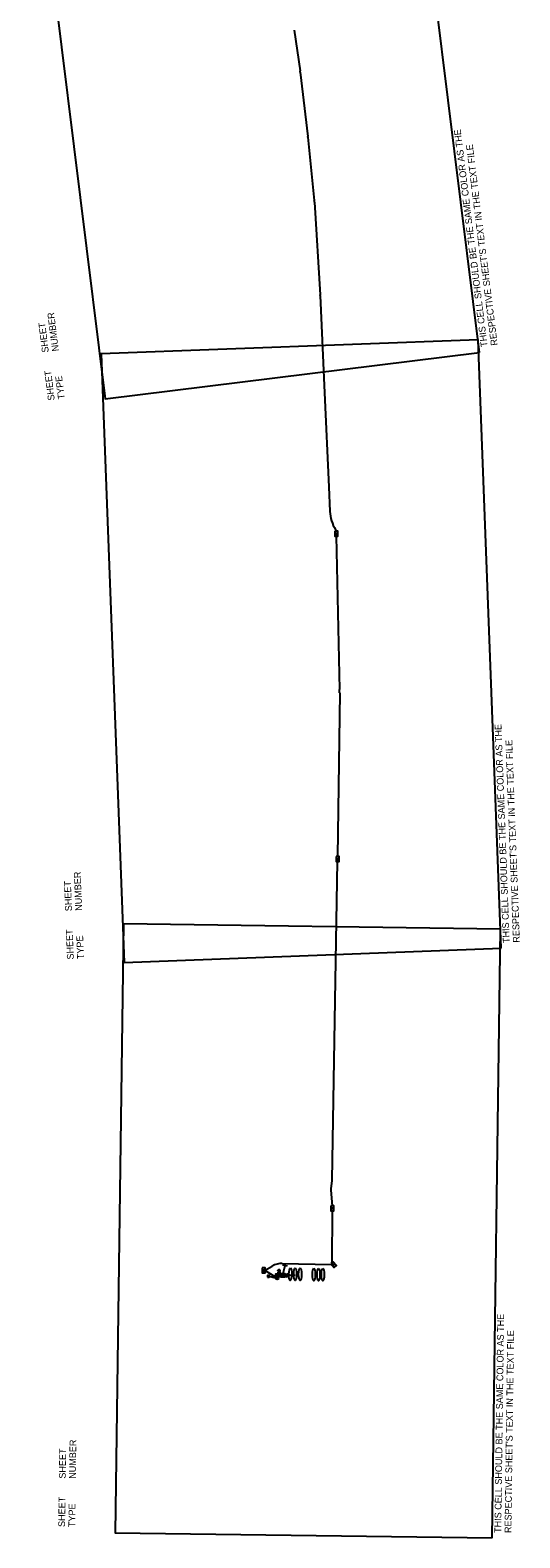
# Model space of a CAD drawing. Extents: x 601462 to 605493, y 331960 to 402715.
# Drawn here: x 604228 to 605493, y 331960 to 335860 of the extents above; entities that cross this region are included whole.
import ezdxf

# ---------------------------------------------------------------- set-up
doc = ezdxf.new("R2010")
doc.units = 0
for name, color, linetype in [('P_FTMS', 7, 'Continuous'), ('P_FTMSConduit', 7, 'Continuous'), ('P_MISC_TXT_2A (Construction)', 7, 'Continuous'), ('P_MISC_TXT_2B (Construction)', 7, 'Continuous')]:
    doc.layers.add(name, color=color, linetype=linetype)

# ---------------------------------------------------------------- blocks, each defined once
blk = doc.blocks.new('FMD')
at = {"layer": 'P_FTMS'}
for p, q in [((17, 18), (-17, 18)), ((-16, 16), (-16, 18)), ((16, 16), (-16, 16)), ((-15, 15), (-15, 20)), ((15, 19), (-15, 19)), ((15, 15), (-15, 15)), ((14, 20), (-14, 20)), ((13, 22), (-13, 22)), ((-13, 13), (-13, 21)), ((13, 13), (-13, 13)), ((-12, 12), (-12, 23)), ((12, 12), (-12, 12)), ((11, 23), (-11, 23)), ((10, 25), (-10, 25)), ((-10, 10), (-10, 24)), ((10, 10), (-10, 10)), ((-9, 9), (-9, 26)), ((9, 9), (-9, 9)), ((8, 26), (-8, 26)), ((7, 28), (-7, 28)), ((-7, 7), (-7, 27)), ((7, 7), (-7, 7)), ((-6, 6), (-6, 29)), ((6, 6), (-6, 6)), ((5, 29), (-5, 29)), ((4, 31), (-4, 31)), ((-4, 4), (-4, 30)), ((4, 4), (-4, 4)), ((-3, 3), (-3, 32)), ((3, 3), (-3, 3)), ((2, 32), (-2, 32)), ((1, 34), (-1, 34)), ((-1, 1), (-1, 33)), ((1, 1), (-1, 1)), ((0, 0), (0, 34)), ((1, 1), (1, 33)), ((3, 3), (3, 32)), ((4, 4), (4, 30)), ((6, 6), (6, 29)), ((7, 7), (7, 27)), ((9, 9), (9, 26)), ((10, 10), (10, 24)), ((12, 12), (12, 23)), ((13, 13), (13, 21)), ((15, 15), (15, 20)), ((16, 16), (16, 18))]:
    blk.add_line(p, q, dxfattribs=at)
blk.add_lwpolyline([(-17, 17), (0, 34), (17, 17), (0, 0)], close=True, dxfattribs=at)
blk = doc.blocks.new('FMB')
at = {"layer": 'P_FTMS'}
for p, q in [((24, -24), (-24, 24)), ((-24, -24), (24, 24))]:
    blk.add_line(p, q, dxfattribs=at)
blk.add_lwpolyline([(24, -24), (24, 24), (-24, 24), (-24, -24)], close=True, dxfattribs=at)
blk = doc.blocks.new('_U259')
at = {"layer": 'P_FTMS'}
for points in [[(-15, -7), (7, -15), (0, 0)], [(15, 7), (-7, 15), (0, 0)]]:
    blk.add_lwpolyline(points, close=True, dxfattribs=at)
at = {"layer": 'P_FTMS', "xscale": 0.4713263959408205, "yscale": 0.4713263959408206, "rotation": 70.39802054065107}
blk.add_blockref('FMB', (0, 0), dxfattribs=at)
blk = doc.blocks.new('FMB_1')
at = {"layer": 'P_FTMS'}
for p, q in [((24, -24), (-24, 24)), ((-24, -24), (24, 24))]:
    blk.add_line(p, q, dxfattribs=at)
blk.add_lwpolyline([(24, -24), (24, 24), (-24, 24), (-24, -24)], close=True, dxfattribs=at)
blk = doc.blocks.new('FTMS_FCV')
at = {"layer": 'P_FTMS'}
blk.add_line((13, 16), (1, -22), dxfattribs=at)
blk.add_lwpolyline([(39, 24), (-39, 24), (-39, -24), (39, -24)], close=True, dxfattribs=at)
blk.add_lwpolyline([(-12, 16), (1, -22)], dxfattribs=at)
blk = doc.blocks.new('FTMS_FERA')
at = {"layer": 'P_FTMS'}
for p, q in [((-65, 37), (-65, -37)), ((65, 0), (-65, 0))]:
    blk.add_line(p, q, dxfattribs=at)

msp = doc.modelspace()

# ---------------------------------------------------------------- linework, layer by layer
at = {"layer": 'P_FTMS'}
for p, q in [((604871.4, 332643.7), (604866.8, 332639.2)), ((604870.4, 332643.7), (604866.8, 332640.2)), ((604870.8, 332643.7), (604866.8, 332639.9)), ((604871.1, 332643.7), (604866.8, 332639.6)), ((604866.8, 332640.4), (604871.3, 332635.8)), ((604866.8, 332640), (604871, 332635.8)), ((604866.8, 332639.7), (604870.7, 332635.8)), ((604866.8, 332639.4), (604870.3, 332635.8)), ((604870, 332643.7), (604866.9, 332640.7)), ((604871.7, 332643.6), (604866.9, 332639)), ((604872, 332643.6), (604866.9, 332638.7)), ((604866.9, 332640.6), (604871.6, 332635.8)), ((604866.9, 332639), (604869.9, 332635.9)), ((604869.5, 332643.5), (604867, 332641.1)), ((604872.2, 332643.5), (604867, 332638.4)), ((604867, 332640.9), (604871.8, 332635.9)), ((604867, 332638.5), (604869.4, 332636)), ((604872.5, 332643.4), (604867.1, 332638.2)), ((604867.1, 332641.2), (604872.1, 332636)), ((604872.7, 332643.3), (604867.2, 332638)), ((604867.2, 332641.4), (604872.3, 332636.1)), ((604868.9, 332643.2), (604867.3, 332641.7)), ((604872.9, 332643.1), (604867.3, 332637.7)), ((604867.3, 332641.6), (604872.6, 332636.2)), ((604867.3, 332637.8), (604868.8, 332636.3)), ((604867.4, 332641.9), (604872.8, 332636.3)), ((604873.1, 332643), (604867.5, 332637.5)), ((604867.5, 332642.1), (604873, 332636.4)), ((604873.3, 332642.9), (604867.6, 332637.3)), ((604867.7, 332642.3), (604873.2, 332636.6)), ((604873.5, 332642.7), (604867.8, 332637.1)), ((604867.8, 332642.4), (604873.4, 332636.7)), ((604873.6, 332642.5), (604867.9, 332637)), ((604868, 332642.6), (604873.6, 332636.9)), ((604873.8, 332642.4), (604868.1, 332636.8)), ((604868.2, 332642.8), (604873.7, 332637.1)), ((604874, 332642.2), (604868.3, 332636.6)), ((604868.4, 332642.9), (604873.9, 332637.2)), ((604874.1, 332642), (604868.5, 332636.5)), ((604868.6, 332643.1), (604874, 332637.4)), ((604874.2, 332641.8), (604868.7, 332636.4)), ((604868.8, 332643.2), (604874.2, 332637.6)), ((604874.4, 332641.5), (604868.9, 332636.2)), ((604868.9, 332634.4), (604869.9, 332635.9)), ((604869, 332643.3), (604874.3, 332637.9)), ((604874.5, 332641.3), (604869.1, 332636.1)), ((604869.2, 332643.4), (604874.4, 332638.1)), ((604874.5, 332641.1), (604869.4, 332636)), ((604869.5, 332643.5), (604874.5, 332638.3)), ((604874.6, 332640.8), (604869.6, 332635.9)), ((604869.7, 332643.6), (604874.6, 332638.6)), ((604874.7, 332640.5), (604869.9, 332635.9)), ((604870, 332643.7), (604874.7, 332638.8)), ((604874.7, 332640.3), (604870.2, 332635.8)), ((604870.3, 332643.7), (604874.7, 332639.1)), ((604874.8, 332639.9), (604870.5, 332635.8)), ((604870.6, 332643.7), (604874.8, 332639.4)), ((604874.8, 332639.6), (604870.8, 332635.8)), ((604870.9, 332643.7), (604874.8, 332639.8)), ((604874.7, 332639.2), (604871.2, 332635.8)), ((604871.3, 332643.7), (604874.8, 332640.1)), ((604874.7, 332638.9), (604871.6, 332635.8)), ((604871.7, 332643.6), (604874.7, 332640.6)), ((604874.5, 332638.4), (604872.1, 332636)), ((604872.2, 332643.5), (604874.6, 332641)), ((604874.2, 332637.8), (604872.7, 332636.2)), ((604872.8, 332643.2), (604874.3, 332641.7)), ((604881.8, 332643.6), (604874.7, 332636.8)), ((604882.1, 332643.6), (604874.7, 332636.4)), ((604882.4, 332643.6), (604874.7, 332636.1)), ((604882.8, 332643.6), (604874.7, 332635.8)), ((604874.7, 332636.7), (604875.7, 332635.7)), ((604874.7, 332636.3), (604875.4, 332635.7)), ((604874.7, 332636), (604875, 332635.7)), ((604875, 332643.7), (604874.8, 332643.6)), ((604876.7, 332643.7), (604874.8, 332641.9)), ((604875.3, 332643.7), (604874.8, 332643.2)), ((604877, 332643.7), (604874.8, 332641.5)), ((604875.6, 332643.7), (604874.8, 332642.9)), ((604877.3, 332643.7), (604874.8, 332641.2)), ((604876, 332643.7), (604874.8, 332642.6)), ((604877.7, 332643.7), (604874.8, 332640.9)), ((604876.3, 332643.7), (604874.8, 332642.2)), ((604878, 332643.7), (604874.8, 332640.5)), ((604878.4, 332643.6), (604874.8, 332640.2)), ((604880.1, 332643.6), (604874.8, 332638.5)), ((604878.7, 332643.6), (604874.8, 332639.8)), ((604880.4, 332643.6), (604874.8, 332638.1)), ((604879, 332643.6), (604874.8, 332639.5)), ((604880.7, 332643.6), (604874.8, 332637.8)), ((604879.4, 332643.6), (604874.8, 332639.2)), ((604881.1, 332643.6), (604874.8, 332637.5)), ((604879.7, 332643.6), (604874.8, 332638.8)), ((604881.4, 332643.6), (604874.8, 332637.1)), ((604874.8, 332643.5), (604882.5, 332635.6)), ((604874.8, 332643.1), (604882.2, 332635.6)), ((604874.8, 332642.8), (604881.8, 332635.6)), ((604874.8, 332642.5), (604881.5, 332635.6)), ((604874.8, 332642.1), (604881.2, 332635.6)), ((604874.8, 332641.8), (604880.8, 332635.6)), ((604874.8, 332641.4), (604880.5, 332635.6)), ((604874.8, 332641.1), (604880.1, 332635.6)), ((604874.8, 332640.8), (604879.8, 332635.6)), ((604874.8, 332640.4), (604879.5, 332635.6)), ((604874.8, 332640.1), (604879.1, 332635.6)), ((604874.8, 332639.7), (604878.8, 332635.6)), ((604874.8, 332639.4), (604878.4, 332635.6)), ((604874.8, 332639.1), (604878.1, 332635.6)), ((604874.8, 332638.7), (604877.8, 332635.7)), ((604874.8, 332638.4), (604877.4, 332635.7)), ((604874.8, 332638), (604877.1, 332635.7)), ((604874.8, 332637.7), (604876.7, 332635.7)), ((604874.8, 332637.4), (604876.4, 332635.7)), ((604874.7, 332637), (604876.1, 332635.7)), ((604875, 332643.7), (604882.9, 332635.6)), ((604883.1, 332643.6), (604875, 332635.7)), ((604875.3, 332643.7), (604883.2, 332635.6)), ((604883.4, 332643.6), (604875.3, 332635.7)), ((604875.6, 332643.7), (604883.5, 332635.6)), ((604883.8, 332643.6), (604875.7, 332635.7)), ((604876, 332643.7), (604883.9, 332635.6)), ((604884.1, 332643.6), (604876, 332635.7)), ((604876.3, 332643.7), (604884.2, 332635.6)), ((604884.5, 332643.6), (604876.4, 332635.7)), ((604876.7, 332643.7), (604884.5, 332635.6)), ((604884.8, 332643.6), (604876.7, 332635.7)), ((604877, 332643.7), (604884.9, 332635.6)), ((604885.1, 332643.6), (604877, 332635.7)), ((604877.3, 332643.7), (604885.2, 332635.6)), ((604885.5, 332643.5), (604877.4, 332635.7)), ((604877.7, 332643.7), (604885.6, 332635.5)), ((604885.8, 332643.5), (604877.7, 332635.7)), ((604878, 332643.7), (604885.9, 332635.5)), ((604886.2, 332643.5), (604878.1, 332635.6)), ((604878.4, 332643.6), (604886.2, 332635.5)), ((604886.5, 332643.5), (604878.4, 332635.6)), ((604878.7, 332643.6), (604886.6, 332635.5)), ((604886.8, 332643.5), (604878.7, 332635.6)), ((604879, 332643.6), (604886.7, 332635.7)), ((604886.8, 332643.2), (604879.1, 332635.6)), ((604879.6, 332639.6), (604879.3, 332639.6)), ((604879.4, 332643.6), (604886.7, 332636.1)), ((604886.8, 332642.9), (604879.4, 332635.6)), ((604879.6, 332639.6), (604879.6, 332639.6)), ((604879.7, 332643.6), (604886.7, 332636.4)), ((604886.8, 332642.5), (604879.8, 332635.6)), ((604880.1, 332643.6), (604886.7, 332636.7)), ((604886.8, 332642.2), (604880.1, 332635.6)), ((604880.4, 332643.6), (604886.8, 332637.1)), ((604886.8, 332641.8), (604880.4, 332635.6)), ((604880.7, 332643.6), (604886.8, 332637.4)), ((604886.8, 332641.5), (604880.8, 332635.6)), ((604881.1, 332643.6), (604886.8, 332637.8)), ((604886.8, 332641.2), (604881.1, 332635.6)), ((604881.4, 332643.6), (604886.8, 332638.1)), ((604886.8, 332640.8), (604881.4, 332635.6)), ((604881.8, 332643.6), (604886.8, 332638.4)), ((604886.8, 332640.5), (604881.8, 332635.6)), ((604882.1, 332643.6), (604886.8, 332638.8)), ((604886.8, 332640.1), (604882.1, 332635.6)), ((604882.4, 332643.6), (604886.8, 332639.1)), ((604886.8, 332639.8), (604882.5, 332635.6)), ((604882.8, 332643.6), (604886.8, 332639.5)), ((604886.8, 332639.5), (604882.8, 332635.6)), ((604883.1, 332643.6), (604886.8, 332639.8)), ((604886.8, 332639.1), (604883.1, 332635.6)), ((604883.4, 332643.6), (604886.8, 332640.1)), ((604886.8, 332638.8), (604883.5, 332635.6)), ((604883.8, 332643.6), (604886.8, 332640.5)), ((604886.8, 332638.4), (604883.8, 332635.6)), ((604884.1, 332643.6), (604886.8, 332640.8)), ((604886.8, 332638.1), (604884.2, 332635.6)), ((604884.5, 332643.6), (604886.8, 332641.2)), ((604886.8, 332637.8), (604884.5, 332635.6)), ((604884.8, 332643.6), (604886.8, 332641.5)), ((604886.8, 332637.4), (604884.8, 332635.6)), ((604885.1, 332643.6), (604886.8, 332641.8)), ((604886.8, 332637.1), (604885.2, 332635.6)), ((604885.5, 332643.5), (604886.8, 332642.2)), ((604886.7, 332636.7), (604885.5, 332635.5)), ((604885.8, 332643.5), (604886.8, 332642.5)), ((604886.7, 332636.4), (604885.9, 332635.5)), ((604886.2, 332643.5), (604886.8, 332642.9)), ((604886.7, 332636.1), (604886.2, 332635.5)), ((604886.5, 332643.5), (604886.8, 332643.2)), ((604886.7, 332635.7), (604886.5, 332635.5)), ((604886.8, 332639.5), (604890.8, 332639.5)), ((604895.1, 332640.9), (604890.7, 332636.7)), ((604895.3, 332640.8), (604890.7, 332636.3)), ((604895.5, 332640.7), (604890.7, 332636)), ((604895.8, 332640.5), (604890.7, 332635.7)), ((604890.7, 332636.9), (604891.6, 332636)), ((604890.7, 332636.5), (604891.4, 332635.9)), ((604890.7, 332636.2), (604891.2, 332635.8)), ((604890.7, 332635.9), (604891, 332635.6)), ((604890.7, 332635.5), (604890.7, 332635.5)), ((604890.8, 332643.5), (604890.8, 332643.5)), ((604891.1, 332643.3), (604890.8, 332643.1)), ((604890.8, 332643.3), (604895.7, 332638.3)), ((604891.3, 332643.2), (604890.8, 332642.8)), ((604891.5, 332643.1), (604890.8, 332642.4)), ((604891.7, 332643), (604890.8, 332642.1)), ((604890.8, 332643), (604895.5, 332638.2)), ((604891.9, 332642.8), (604890.8, 332641.8)), ((604892.1, 332642.7), (604890.8, 332641.4)), ((604890.8, 332642.7), (604895.3, 332638.1)), ((604892.3, 332642.6), (604890.8, 332641.1)), ((604892.6, 332642.5), (604890.8, 332640.7)), ((604892.8, 332642.3), (604890.8, 332640.4)), ((604890.8, 332642.3), (604895.1, 332637.9)), ((604893, 332642.2), (604890.8, 332640.1)), ((604893.2, 332642.1), (604890.8, 332639.7)), ((604890.8, 332642), (604894.9, 332637.8)), ((604893.4, 332641.9), (604890.8, 332639.4)), ((604893.6, 332641.8), (604890.8, 332639)), ((604893.8, 332641.7), (604890.8, 332638.7)), ((604894.1, 332641.6), (604890.8, 332638.4)), ((604890.8, 332641.6), (604894.6, 332637.7)), ((604894.3, 332641.4), (604890.8, 332638)), ((604894.5, 332641.3), (604890.8, 332637.7)), ((604890.8, 332641.3), (604894.4, 332637.6)), ((604894.7, 332641.2), (604890.8, 332637.4)), ((604894.9, 332641.1), (604890.8, 332637)), ((604890.8, 332641), (604894.2, 332637.5)), ((604890.8, 332640.6), (604894, 332637.3)), ((604890.8, 332640.3), (604893.8, 332637.2)), ((604890.8, 332639.9), (604893.6, 332637.1)), ((604890.8, 332639.6), (604893.3, 332637)), ((604890.8, 332639.3), (604893.1, 332636.9)), ((604890.8, 332638.9), (604892.9, 332636.7)), ((604890.8, 332638.6), (604892.7, 332636.6)), ((604890.8, 332638.2), (604892.5, 332636.5)), ((604890.8, 332637.9), (604892.3, 332636.4)), ((604890.8, 332637.6), (604892, 332636.2)), ((604890.8, 332637.2), (604891.8, 332636.1)), ((604896, 332640.4), (604891.2, 332635.8)), ((604891.3, 332643.2), (604895.9, 332638.4)), ((604896.2, 332640.3), (604892, 332636.2)), ((604892.1, 332642.7), (604896.2, 332638.6)), ((604896.4, 332640.2), (604892.8, 332636.7)), ((604892.9, 332642.3), (604896.4, 332638.7)), ((604896.6, 332640), (604893.6, 332637.1)), ((604893.7, 332641.8), (604896.6, 332638.8)), ((604896.8, 332639.9), (604894.4, 332637.6)), ((604894.5, 332641.3), (604896.8, 332638.9)), ((604897, 332639.8), (604895.2, 332638)), ((604895.3, 332640.8), (604897, 332639)), ((604896.1, 332640.3), (604897.2, 332639.2)), ((604897.3, 332639.7), (604896.1, 332638.5)), ((604896.9, 332639.9), (604897.5, 332639.3)), ((604897.5, 332639.5), (604896.9, 332638.9)), ((604897.7, 332639.4), (604897.7, 332639.4)), ((604912.9, 332639.2), (604897.7, 332639.4))]:
    msp.add_line(p, q, dxfattribs=at)
for points in [[(604874.7, 332635.7), (604886.7, 332635.5), (604886.8, 332643.5), (604874.8, 332643.7)], [(604890.8, 332643.5), (604890.7, 332635.5), (604897.7, 332639.4)]]:
    msp.add_lwpolyline(points, close=True, dxfattribs=at)
for centre, radius in [((604865.9, 332632.2), 3.75), ((604870.8, 332639.7), 4)]:
    msp.add_circle(centre, radius, dxfattribs=at)
for centre, start, end in [((604865.8, 332627.7), 36.2095, 142.4651), ((604865.9, 332636.7), 216.2095, 322.4651)]:
    msp.add_arc(centre, 3.75, start, end, dxfattribs=at)
for centre in [(604900.2, 332642.3), (604912.6, 332642.2), (604925.4, 332642), (604961, 332641.5), (604973, 332641.4), (604984.3, 332641.2)]:
    msp.add_ellipse(centre, major_axis=(0.2, 16), ratio=0.23471, dxfattribs=at)
at = {"layer": 'P_FTMSConduit'}
for p, q in [((604909.7, 335860.1), (604925.4, 335754.5)), ((604925.8, 335751.4), (604945.3, 335585)), ((604945.4, 335583.6), (604962.2, 335419.5)), ((604962.5, 335415.5), (604977.4, 335175.2)), ((604977.5, 335173.6), (604988.8, 334921.7)), ((604988.8, 334921.7), (604999.8, 334679.1)), ((604999.8, 334679.1), (605002.7, 334615.3)), ((605017, 334567.9), (605019.3, 334564.2)), ((605027.7, 334154.9), (605019.3, 334551.3)), ((605027.7, 334146.4), (605022.4, 333722.4)), ((605008, 332886.7), (605022.4, 333709.6)), ((605004.8, 332860), (605008.5, 332819.3)), ((605007.8, 332884.9), (605004.9, 332863.4)), ((605008, 332672), (605008.9, 332806.5)), ((604835.1, 332652.3), (604853.2, 332663)), ((604879.5, 332669.9), (605006.4, 332667.7)), ((604835.5, 332652.2), (604862.9, 332634.5)), ((604845.5, 332637.3), (604862.1, 332632.6)), ((604863.3, 332635), (604861.5, 332639.1))]:
    msp.add_line(p, q, dxfattribs=at)
for centre, radius, start, end in [((604826.5, 335739.8), 100, 6.6653, 8.4708), ((604846, 335573.4), 100, 5.8282, 6.6653), ((604862.7, 335409.3), 100, 3.5391, 5.8282), ((604877.6, 335169.1), 100, 2.5856, 3.5391), ((605102.6, 334619.8), 100, 182.5856, 211.2173), ((604777.7, 334149.6), 250, 359.2764, 1.206), ((605019.7, 332861.3), 15, 172.2413, 185.1859), ((604993, 332886.9), 15, 352.2413, 358.9961), ((604878.6, 332619.9), 50, 88.9716, 120.5041)]:
    msp.add_arc(centre, radius, start, end, dxfattribs=at)
at = {"layer": 'P_MISC_TXT_2A (Construction)'}
for points in [[(605389.3, 335026.4), (605195.3, 336589.4), (604227.7, 336469.3), (604421.8, 334906.3)], [(605422.3, 331960.3), (605443.8, 333535.1), (604468.9, 333548.4), (604447.4, 331973.6)]]:
    msp.add_lwpolyline(points, close=True, dxfattribs=at)
at = {"layer": 'P_MISC_TXT_2B (Construction)'}
msp.add_lwpolyline([(605445.1, 333485.4), (605385.6, 335059.3), (604411.3, 335022.5), (604470.8, 333448.6)], close=True, dxfattribs=at)

# ---------------------------------------------------------------- block references
at = {"layer": 'P_FTMS'}
for name, p, xscale, yscale, rotation in [('FTMS_FCV', (605019.3, 334557.7), 0.16404166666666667, 0.16404166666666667, 90), ('FTMS_FCV', (605022.4, 333716), 0.16404166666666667, 0.16404166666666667, 90), ('FTMS_FCV', (605008.5, 332812.9), 0.16404166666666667, 0.16404166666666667, 90), ('FTMS_FCV', (604831.5, 332652.2), 0.16404166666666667, 0.16404166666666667, 90), ('FTMS_FERA', (604884, 332654), 0.1640416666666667, 0.16404166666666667, -103.91663607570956), ('FTMS_FCV', (605012.1, 332667.1), 0.16404166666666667, 0.1640416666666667, 129.72472144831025), ('FMB_1', (604843.5, 332636.9), 0.08202083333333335, 0.08202083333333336, -90.78171137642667), ('_U259', (604864.5, 332639.9), 0.19685000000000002, 0.19685, 19.81860041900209), ('FMD', (604868, 332646.6), 0.1640416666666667, 0.16404166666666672, -90.78171137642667), ('FMD', (604868.1, 332652.2), 0.1640416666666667, 0.16404166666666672, -90.78171137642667)]:
    msp.add_blockref(name, p, dxfattribs=dict(at, xscale=xscale, yscale=yscale, rotation=rotation))

# ---------------------------------------------------------------- texts
at = {"layer": 'P_MISC_TXT_2A (Construction)'}
for s, rotation, p in [('THIS CELL SHOULD BE THE SAME COLOR AS THE', 97.0771, (605410.2, 335042.1)), ("RESPECTIVE SHEET'S TEXT IN THE TEXT FILE", 97.0771, (605436.2, 335045.3)), ('NUMBER', 97.0771, (604301.9, 335030.5)), ('SHEET', 97.0771, (604275.9, 335027.2)), ('SHEET', 97.0771, (604291.3, 334903.2)), ('TYPE', 97.0771, (604317.3, 334906.4)), ('THIS CELL SHOULD BE THE SAME COLOR AS THE', 89.2183, (605445.1, 331972.9)), ("RESPECTIVE SHEET'S TEXT IN THE TEXT FILE", 89.2183, (605471.4, 331972.6)), ('SHEET', 89.2183, (604319.5, 332113.3)), ('NUMBER', 89.2183, (604345.7, 332112.9)), ('SHEET', 89.2183, (604317.8, 331988.3)), ('TYPE', 89.2183, (604344, 331988))]:
    msp.add_text(s, height=17.5, rotation=rotation, dxfattribs=at).set_placement(p)
at = {"layer": 'P_MISC_TXT_2B (Construction)'}
for s, p in [('THIS CELL SHOULD BE THE SAME COLOR AS THE', (605467.2, 333499.2)), ("RESPECTIVE SHEET'S TEXT IN THE TEXT FILE", (605493.5, 333500.2)), ('NUMBER', (604362, 333582.5)), ('SHEET', (604335.8, 333581.5)), ('SHEET', (604340.5, 333456.6)), ('TYPE', (604366.8, 333457.6))]:
    msp.add_text(s, height=17.5, rotation=92.1661, dxfattribs=at).set_placement(p)

doc.saveas('drawing.dxf')
